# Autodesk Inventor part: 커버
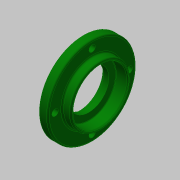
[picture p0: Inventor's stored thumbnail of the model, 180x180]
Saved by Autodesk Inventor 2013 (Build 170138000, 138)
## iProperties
Created: 2018-11
Part Number: 커버
Material: 알루미늄 6061
Document SubType Name: Modeling
Designer: mduedu
Density: 1 g/cm^3
Author: mduedu
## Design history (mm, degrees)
sketch "스케치1"
  geometry: L1 (0, 0)-(3, 0); L2 (3, 0)-(3, 20); L3 (3, 20)-(0, 20); L4 (0, 20)-(0, 0); L5 (3, 0)-(9, 0); L6 (9, 0)-(9, 31); L7 (9, 31)-(3, 31); L8 (3, 31)-(3, 0); L9 (9, 0)-(15, 0); L10 (15, 0)-(15, 21); L11 (15, 21)-(9, 21); L12 (9, 21)-(9, 0)
  constraints: 24 end point, 6 parallel, 3 horizontal, 3 perpendicular
  dimensions: "d0" = 62 diameter of L7 L5; "d2" = 42 diameter of L11 L9; "d3" = 40 diameter of L3 L1; "d4" = 3 distance of L2.end L3.end; "d5" = 6 distance of L6.end L7.end; "d6" = 15 distance between parallel lines of L10 L4
revolve "회전1" sketch "스케치1" stored, may be unused: angle "d7" = 90 deg
sketch "스케치2"
  geometry: L1 (0, -20)-(0, 20) reference; L2 (0, 20)-(3, 20) reference; L3 (3, 20)-(3, 31) reference; L4 (3, 31)-(9, 31) reference; L5 (9, 31)-(9, 21) reference; L6 (9, 21)-(15, 21) reference; L7 (15, 21)-(15, -21) reference; L8 (15, -21)-(9, -21) reference; L9 (9, -21)-(9, -31) reference; L10 (9, -31)-(3, -31) reference; L11 (3, -31)-(3, -20) reference; L12 (3, -20)-(0, -20) reference; L13 (0, 0)-(3, 0); L14 (3, 0)-(3, 16.5); L15 (3, 16.5)-(0, 16.5); L16 (0, 16.5)-(0, 0); L17 (3, 0)-(6.7, 0); L18 (6.7, 0)-(6.7, 14); L19 (6.7, 14)-(3, 14); L20 (3, 14)-(3, 0); L21 (6.7, 0)-(15, 0); L22 (15, 0)-(15, 19); L23 (15, 19)-(6.7, 19); L24 (6.7, 19)-(6.7, 0)
  constraints: 24 end point, 6 parallel, 3 horizontal, 3 perpendicular, 1 point on line
  dimensions: "d8" = 38 diameter of L23 L21; "d10" = 28 diameter of L19 L17; "d11" = 33 diameter of L15 L13; "d12" = 3 distance of L14.end L15.end; "d13" = 8.3 distance of L22.end L23.end
revolve "회전2" sketch "스케치2" stored, may be unused: angle "d14" = 90 deg
fillet "모깎기1" dims "d15" = 0.3
chamfer "모따기1" distance "d16" = 0.8; stored, may be unused: second distance "d17" = 2, angle "d18" = 30 deg
fillet "모깎기2" dims "d19" = 1
chamfer "모따기2" distance "d20" = 0.5; stored, may be unused: second distance "d21" = 2, angle "d22" = 30 deg
sketch "스케치3" dims "d23" = 52
  geometry: 6 further points
  constraints: 2 vertical alignment, 1 coincident, 7 other
  dimensions: "d26" = 360 deg dimension on point (0, 0) point (0, 26) (derived)
sketch "스케치4"
  geometry: 4 further points
  constraints: 4 other
hole "구멍1" sketch "스케치4" at (-26, 0), (0, -26), (26, 0), (0, 26) diameter "d28" = 4.5; stored, may be unused: countersink angle "d32" = 90 deg, drill point angle "d34" = 0 deg; dims "d29" = 6, "d30" = 8, "d31" = 4.6, "d33" = 8
node "솔리드1"
node "절단 모서리 투영1"
